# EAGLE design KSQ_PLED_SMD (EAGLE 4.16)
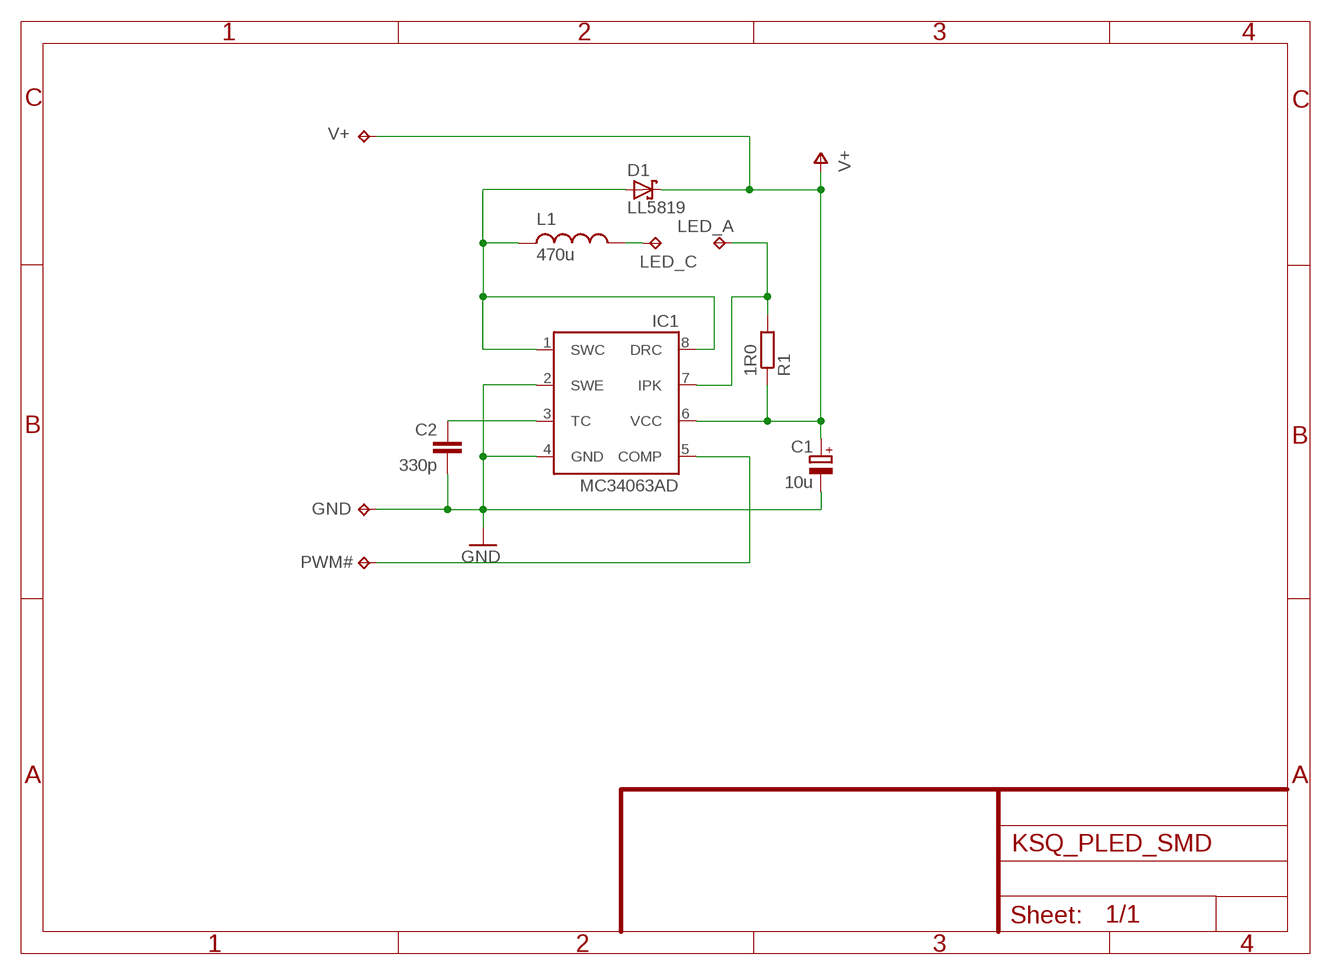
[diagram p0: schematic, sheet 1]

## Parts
C1  10u  CPOL-EUSMCD  [SMC_D]
C2  330p  C-EUC1206  [C1206]
D1  LL5819  DIODESCHOTTKY  [MELF-MLL41]
GND  TPB2,54  [B2,54]
IC1  MC34063AD  [SO08]
L1  470u  MSS1260  [MSS1260]
LED_A  TPB2,54  [B2,54]
LED_C  TPB2,54  [B2,54]
PWM#  TPB2,54  [B2,54]
R1  1R0  R-EU_R1206  [R1206]
V+  TPB2,54  [B2,54]

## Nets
GND: C1.- C2.2 GND.PP(TP) IC1.2(SWE) IC1.4(GND)
N$1: D1.A IC1.1(SWC) IC1.8(DRC) L1.P$2
N$2: L1.P$1 LED_C.PP(TP)
N$4: IC1.7(IPK) LED_A.PP(TP) R1.2
N$7: C2.1 IC1.3(TC)
N$9: IC1.5(COMP) PWM#.PP(TP)
V+: C1.+ D1.C IC1.6(VCC) R1.1 V+.PP(TP)

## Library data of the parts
C1 = rcl:CPOL-EU: POLARIZED CAPACITOR, European symbol
C2 = rcl:C-EU: CAPACITOR, European symbol
D1 = Brunner:DIODESCHOTTKY
GND LED_A LED_C PWM# V+ = testpad:TP
IC1 = v-reg-3:MC34063A: 1.5A Step-Up/Down/Inverting Switching Regulator NPN Darlington Switch, Vin 3V to 40V, Current Limiter Input, adjustable Frequency up to 100kHz
L1 = inductor-coilcraft:MSS1260: SMT Power Inductor
R1 = rcl:R-EU_: RESISTOR, European symbol

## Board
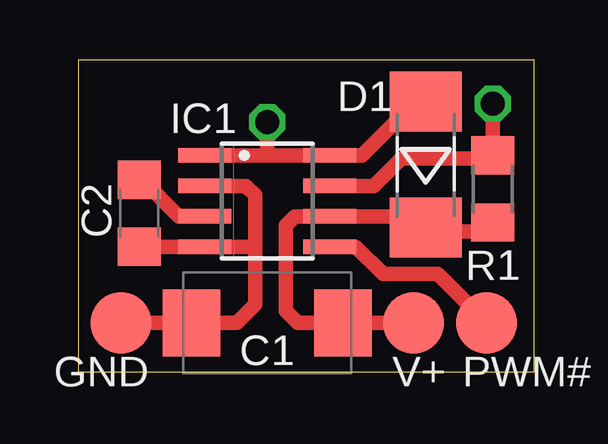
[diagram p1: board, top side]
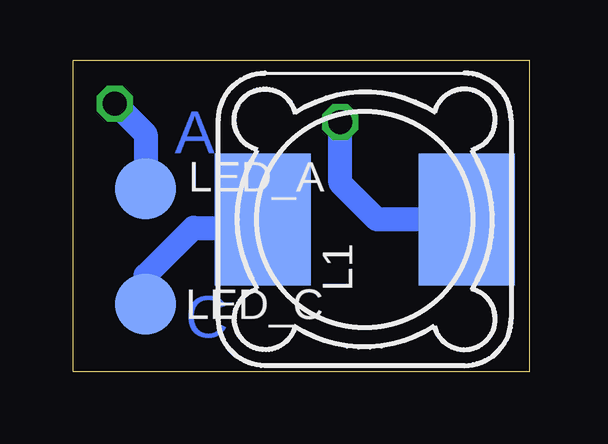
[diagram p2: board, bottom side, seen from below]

Size 19 x 13 mm. Coordinates in mm from the lower left corner, seen from the top.
Outline: 0,0 19,0 19,13 0,13 0,0
Copper layers (1*16): Top 0.035mm / dielectric 1.5mm / Bottom 0.035mm
Design rules "default": minimum track width 10mil, minimum drill 24mil, track to track 14mil, track to pad 14mil, pad to pad 14mil, via to via 14mil, smd to smd 14mil, copper to edge 35mil, drill to drill 8mil, minimum pad ring 20mil, minimum via ring 8mil, stop-mask expansion 4mil, vias tented up to drill 0mil, thermal gap 10mil

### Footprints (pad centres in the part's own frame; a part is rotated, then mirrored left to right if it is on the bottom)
SMC_D = smd 2.4 x 2.8: + -3.15,0; - 3.15,0
C1206 = smd 1.6 x 1.8: 1 -1.4,0; 2 1.4,0
MELF-MLL41 = smd 2.5 x 3: A 2.625,0; C -2.625,0
B2,54 = smd 2.54 x 2.54: PP 0,0
SO08 = smd 0.6 x 2.2: 1 -1.905,-2.6; 2 -0.635,-2.6; 3 0.635,-2.6; 4 1.905,-2.6; 5 1.905,2.6; 6 0.635,2.6; 7 -0.635,2.6; 8 -1.905,2.6
MSS1260 = smd 5.5 x 4: P$1 0,4.25; P$2 0,-4.25
R1206 = smd 1.6 x 1.8: 1 -1.4,0; 2 1.4,0

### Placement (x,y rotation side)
C1  7.87,2.03 180 top
C2  2.54,6.6 270 top
D1  14.48,8.64 90 top
GND  1.78,2.03 0 top
IC1  7.87,7.11 270 top
L1  6.86,6.35 90 bottom
LED_A  15.99,7.62 0 bottom
LED_C  15.99,2.81 0 bottom
PWM#  17.02,2.03 0 top
R1  17.27,7.62 90 top
V+  13.97,2.03 0 top

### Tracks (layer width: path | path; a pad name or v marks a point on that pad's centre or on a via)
GND
  Top 0.61: 7.37,5.08 7.37,2.79 6.6,2.03 C1.- GND.PP | 7.37,5.08 7.37,7.37 6.99,7.75 IC1.2 | 7.37,5.08 7.24,5.21 IC1.4 2.67,5.21 2.54,5.33 C2.2
N$1  (via drill 1)
  Top 0.61: 7.87,9.02 IC1.1 | 7.87,9.02 IC1.8 11.81,9.02 13.97,11.18 14.22,11.18 14.31,11.26 D1.A | v7.87,10.41 7.87,9.02
  Bottom 1: L1.P$2 6.35,6.35 7.87,7.87 v7.87,10.41
N$2
  Bottom 1: LED_C.PP 15.99,4.01 14,6 11,6 11.11,6.11 L1.P$1
N$4  (via drill 1)
  Top 0.61: IC1.7 12.32,7.75 13.46,8.89 17.27,8.89 | 17.27,8.89 R1.2 | 17.27,8.89 v17.27,11.18
  Bottom 0.61: v17.27,11.18 17.26,11.18
  Bottom 1: LED_A.PP 15.99,9.91 17.26,11.18
N$7
  Top 0.61: C2.1 2.66,8 4.19,6.48 IC1.3
N$9
  Top 0.61: IC1.5 11.56,5.21 12.7,4.06 14.99,4.06 PWM#.PP
V+
  Top 0.61: 14.22,5.84 D1.C | 14.22,5.84 13.59,6.48 IC1.6 9.02,6.48 8.64,6.1 8.64,2.54 9.14,2.03 10.92,2.03 | 10.92,2.03 C1.+ | 10.92,2.03 V+.PP | 17.27,6.35 17.27,6.6 | 17.27,6.35 R1.1 | 14.22,5.84 16.76,5.84 17.27,6.35

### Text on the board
Bottom: A | C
